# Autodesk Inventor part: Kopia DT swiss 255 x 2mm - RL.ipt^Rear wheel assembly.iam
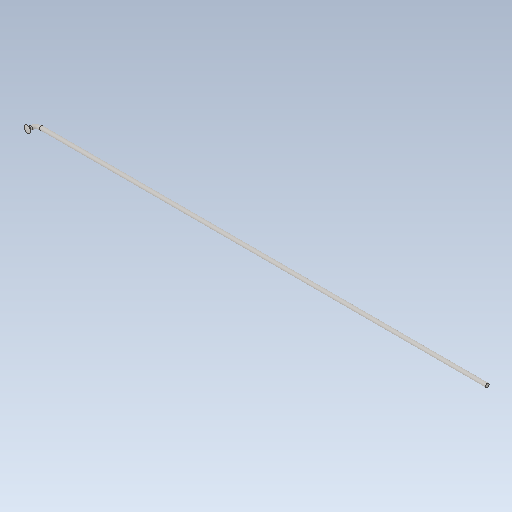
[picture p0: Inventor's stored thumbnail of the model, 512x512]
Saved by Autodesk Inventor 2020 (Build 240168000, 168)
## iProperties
Created: 2017-09
Part Number: Kopia DT swiss 255 x 2mm - RL.ipt^Rear wheel assembly.iam
Material: Ogólny
Document SubType Name: Modeling
Designer: Tomasz
Density: 1 g/cm^3
Appearance: Domyślna
Sending System: SolidWorks 2017
Last Author: Tomasz
Last Saved: 2017-09-11
Author: Tomasz
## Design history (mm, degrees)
feature "DT swiss 255 x 2mm - RL.ipt"
node "Bryła1"
